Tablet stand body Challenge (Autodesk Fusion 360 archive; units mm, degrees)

design "mmTablet stand body Challenge" references "haas minimill"
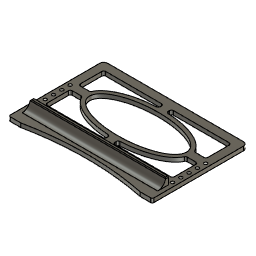
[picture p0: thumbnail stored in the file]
sketch "Sketch1" plane through (0, 0, 0) normal (0, 0, 1) x axis (1, 0, 0)
  line L1 (225.425, 0) -> (0, 0)
  line L2 (225.425, 149.225) -> (225.425, 0)
  line L3 (0, 149.225) -> (225.425, 149.225)
  line L4 (0, 0) -> (0, 149.225)
  point P1 (0, 0)
  point P2 (0, 0)
  point P3 (225.425, 0)
  point P5 (0, 149.225)
  horizontal L1
  vertical L2
  horizontal L3
  vertical L4
  coincident P1 P2
  dimension "d1" distance P2 P3 = 225.425
  dimension "d2" distance P2 P5 = 149.225
extrude "Extrude1" new body sketch "Sketch1" along normal blind 6.35
sketch "Sketch2" plane through (225.425, 0, 0) normal (1, 0, 0) x axis (0, 1, 0)
  line L1 (149.225, 0) -> (0, 0)
  line L2 (149.225, 6.35) -> (149.225, 0)
  line L3 (0, 6.35) -> (149.225, 6.35)
  line L4 (0, 0) -> (0, 6.35)
  line L5 (15.875, 6.35) -> (0, 6.35)
  line L6 (28.575, 6.35) -> (15.875, 6.35)
  line L7 (28.575, 17.907) -> (28.575, 6.35)
  line L8 (31.75, 17.907) -> (28.575, 17.907)
  line L9 (31.75, 6.35) -> (31.75, 17.907)
  line L10 (28.575, 6.35) -> (31.75, 6.35)
  line L11 (27.305, 6.35) -> (28.575, 6.35)
  line L12 (27.305, 16.637) -> (27.305, 6.35)
  line L13 (27.305, 16.637) -> (28.575, 17.907)
  line L14 (34.0111, 17.907) -> (28.575, 17.907)
  point P5 (0, 6.35)
  point P6 (0, 6.35)
  point P11 (31.75, 6.35)
  point P7 (15.875, 6.35)
  point P8 (28.575, 6.35)
  point P9 (28.575, 17.907)
  point P10 (31.75, 17.907)
  point P12 (27.305, 6.35)
  coincident P5 P6
  perpendicular L4 L5
  parallel L3 L6
  perpendicular L6 L7
  perpendicular L7 L8
  coincident L3 P11
  perpendicular L3 L9
  perpendicular L7 L11
  perpendicular L6 L12
  horizontal L14
  dimension "d5" distance P6 P7 = 15.875
  dimension "d6" distance P7 P8 = 12.7
  dimension "d8" distance P8 P9 = 11.557
  dimension "d9" distance P9 P10 = 3.175
  dimension "d10" distance P8 P12 = 1.27
  dimension "d11" angle L13 L14 = 135
extrude "Extrude2" add sketch "Sketch2" profile of L3 L6 L7 L8 L9 L10 L11 L12 L13 against normal blind 225.425
fillet "Fillet1" radius 12.7
sketch "Sketch3" plane through (0, 0, 6.35) normal (0, 0, 1) x axis (-1, 0, 0)
  line L1 (0, -14.8363) -> (-225.425, -14.8363)
  line L2 (0, 0) -> (0, -14.8363)
  line L3 (-225.425, 0) -> (0, 0)
  line L4 (-225.425, -14.8363) -> (-225.425, 0)
  line L5 (-19.05, 0) -> (0, 0)
  line L6 (-206.375, 0) -> (-225.425, 0)
  line L7 (-206.375, 0) -> (-19.05, 0)
  arc A1 centre (-112.7125, 457.2) radius 466.6953 clockwise from (-19.05, 0) to (-206.375, 0)
  point P4 (0, 0)
  point P6 (0, 0)
  point P5 (-225.425, 0)
  point P8 (-225.425, 0)
  point P7 (-19.05, 0)
  point P9 (-206.375, 0)
  point P10 (-112.7125, 457.2)
  coincident P4 P6
  perpendicular L2 L5
  coincident P5 P8
  perpendicular L4 L6
  dimension "d16" distance P6 P7 = 19.05
  dimension "d17" distance P8 P9 = 19.05
  dimension "d18" distance L3 P10 = 457.2
extrude "Extrude3" cut sketch "Sketch3" profile of L3 A1 L7 against normal blind 6.35
sketch "Sketch4" plane through (0, 0, 17.907) normal (0, 0, 1) x axis (-1, 0, 0)
  line L1 (-225.425, -31.75) -> (-225.425, -28.575)
  line L2 (0, -31.75) -> (-225.425, -31.75)
  line L3 (0, -28.575) -> (0, -31.75)
  line L4 (-225.425, -28.575) -> (0, -28.575)
  line L5 (-6.35, -31.75) -> (0, -31.75)
  line L6 (-6.35, -12.7) -> (-6.35, -31.75)
  line L7 (0, -12.7) -> (-6.35, -12.7)
  line L8 (0, -31.75) -> (0, -12.7)
  point P4 (0, -31.75)
  point P6 (0, -31.75)
  point P7 (-6.35, -31.75)
  point P9 (0, -12.7)
  horizontal L5
  vertical L6
  horizontal L7
  vertical L8
  coincident P4 P6
  dimension "d21" distance P6 P7 = 6.35
  dimension "d22" distance P6 P9 = 19.05
work_plane "WorkPlane1"
extrude "Extrude4" cut sketch "Sketch4" profile of L2 L3 L4 L5 L6 L7 L8 to an object
sketch "Sketch5" plane through (0, 0, 17.907) normal (0, 0, 1) x axis (-1, 0, 0)
  line L1 (-6.35, -28.575) -> (-6.35, -31.75)
  line L2 (-225.425, -28.575) -> (-6.35, -28.575)
  line L3 (-225.425, -31.75) -> (-225.425, -28.575)
  line L4 (-6.35, -31.75) -> (-225.425, -31.75)
  line L5 (-219.075, -31.75) -> (-225.425, -31.75)
  line L6 (-219.075, -12.7) -> (-219.075, -31.75)
  line L7 (-225.425, -12.7) -> (-219.075, -12.7)
  line L8 (-225.425, -31.75) -> (-225.425, -12.7)
  point P5 (-225.425, -31.75)
  point P6 (-225.425, -31.75)
  point P7 (-219.075, -31.75)
  point P9 (-225.425, -12.7)
  horizontal L5
  vertical L6
  horizontal L7
  vertical L8
  coincident P5 P6
  dimension "d25" distance P6 P7 = 6.35
  dimension "d26" distance P6 P9 = 19.05
extrude "Extrude5" cut sketch "Sketch5" profile of L2 L3 L4 L5 L6 L7 L8 to an object
chamfer "Chamfer1" distance 1.27
sketch "Sketch6" plane through (0, 0, 6.35) normal (0, 0, 1) x axis (-1, 0, 0)
  line L1 (-225.425, -149.225) -> (-225.425, 0)
  line L2 (0, -149.225) -> (-225.425, -149.225)
  line L3 (0, 0) -> (0, -149.225)
  line L4 (-19.05, 0) -> (0, 0)
  line L5 (-225.425, 0) -> (-206.375, 0)
  line L6 (-219.075, -14.8363) -> (-219.075, -31.75)
  line L7 (-6.35, -14.8363) -> (-219.075, -14.8363)
  line L8 (-6.35, -31.75) -> (-6.35, -14.8363)
  line L9 (-219.075, -31.75) -> (-6.35, -31.75)
  line L10 (-112.7125, -31.75) -> (-112.7125, -149.225)
  line L11 (-225.425, -90.4875) -> (-112.7125, -90.4875)
  curve K1 (-188.9125, -90.4875) -> (-36.5125, -90.4875)
  curve K2 (-112.7125, -122.2375) -> (-112.7125, -58.7375)
  arc A1 centre (-112.7125, 457.2) radius 466.6953 clockwise from (-19.05, 0) to (-206.375, 0)
  closed curve K3 centre (-112.7125, -90.4875)
  point P13 (-112.7125, -149.225)
  point P14 (-112.7125, -31.75)
  point P15 (-112.7125, -90.4875)
  point P18 (-36.5125, -90.4875)
  point P19 (-188.9125, -90.4875)
  point P20 (-112.7125, -58.7375)
  point P21 (-112.7125, -122.2375)
  point P17 (-112.7125, -90.4875)
  point P16 (-225.425, -90.4875)
  midpoint L2 P13
  midpoint L9 P14
  midpoint L10 P15
  perpendicular L10 L11
  coincident K3 P18
  coincident K3 P19
  coincident K3 P20
  coincident K3 P21
  coincident P15 P17
  perpendicular L10 K1
  coincident L1 P16
  dimension "d37" distance K3 = 152.4
  dimension "d38" = 31.75
extrude "Extrude6" cut sketch "Sketch6" profile of L10 L11 K3 no distance stored
sketch "Sketch7" plane through (0, 0, 6.35) normal (0, 0, 1) x axis (-1, 0, 0)
  line L1 (-212.725, -136.525) -> (-12.7, -136.525)
  line L2 (-212.725, -44.45) -> (-212.725, -136.525)
  line L3 (-12.7, -44.45) -> (-212.725, -44.45)
  line L4 (-12.7, -136.525) -> (-12.7, -44.45)
  line L5 (-225.425, -149.225) -> (-225.425, 0)
  line L6 (0, -149.225) -> (-225.425, -149.225)
  line L7 (0, 0) -> (0, -149.225)
  line L8 (-19.05, 0) -> (0, 0)
  line L9 (-225.425, 0) -> (-206.375, 0)
  line L10 (-219.075, -14.8363) -> (-219.075, -31.75)
  line L11 (-6.35, -14.8363) -> (-219.075, -14.8363)
  line L12 (-6.35, -31.75) -> (-6.35, -14.8363)
  line L13 (-219.075, -31.75) -> (-6.35, -31.75)
  line L14 (-106.3625, -90.4875) -> (-112.7125, -90.4875)
  line L15 (-112.7125, -44.45) -> (-112.7125, -90.4875)
  line L16 (-112.7125, -136.525) -> (-112.7125, -90.4875)
  line L17 (-106.3625, -84.1375) -> (-106.3625, -90.4875)
  line L18 (-106.3625, -44.45) -> (-106.3625, -52.5004)
  line L19 (-119.0625, -84.1375) -> (-119.0625, -90.4875)
  line L20 (-119.0625, -44.45) -> (-119.0625, -52.5004)
  line L21 (-106.3625, -122.1271) -> (-106.3625, -90.4875)
  line L22 (-106.3625, -136.525) -> (-106.3625, -128.4746)
  line L23 (-119.0625, -122.1271) -> (-119.0625, -90.4875)
  line L24 (-119.0625, -136.525) -> (-119.0625, -128.4746)
  line L25 (-119.0625, -84.1375) -> (-112.7125, -84.1375)
  line L26 (-212.725, -84.1375) -> (-194.1079, -84.1375)
  line L27 (-119.0625, -96.8375) -> (-112.7125, -96.8375)
  line L28 (-212.725, -96.8375) -> (-194.1079, -96.8375)
  line L29 (-119.0625, -90.4875) -> (-112.7125, -90.4875)
  line L30 (-195.2625, -90.4875) -> (-188.9125, -90.4875)
  line L31 (-38.0521, -84.1375) -> (-112.7125, -84.1375)
  line L32 (-12.7, -84.1375) -> (-31.3171, -84.1375)
  line L33 (-38.0521, -96.8375) -> (-112.7125, -96.8375)
  line L34 (-12.7, -96.8375) -> (-31.3171, -96.8375)
  closed curve K1 centre (-112.7125, -90.4875)
  arc A1 centre (-112.7125, 457.2) radius 466.6953 clockwise from (-19.05, 0) to (-206.375, 0)
  closed curve K2 centre (-112.7125, -90.4875)
  closed curve K3 centre (-112.7125, -90.4875)
  point P6 (-112.7125, -90.4875)
  point P20 (-112.7125, -90.4875)
  point P18 (-112.7125, -90.4875)
  point P21 (-112.7125, -90.4875)
  point P22 (-112.7125, -44.45)
  point P23 (-112.7125, -90.4875)
  point P24 (-112.7125, -136.525)
  point P39 (-106.3625, -84.1375)
  point P41 (-119.0625, -52.5004)
  point P42 (-106.3625, -52.5004)
  point P43 (-106.3625, -122.1271)
  point P44 (-106.3625, -128.4746)
  point P45 (-119.0625, -122.1271)
  point P46 (-119.0625, -128.4746)
  point P47 (-119.0625, -96.8375)
  point P48 (-194.1079, -96.8375)
  point P49 (-194.1079, -84.1375)
  point P50 (-188.9125, -90.4875)
  point P51 (-195.2625, -90.4875)
  point P52 (-38.0521, -84.1375)
  point P53 (-31.3171, -84.1375)
  point P54 (-38.0521, -96.8375)
  point P55 (-31.3171, -96.8375)
  horizontal L1
  vertical L2
  horizontal L3
  vertical L4
  coincident P6 P20
  perpendicular L2 L29
  coincident P18 P21
  midpoint L3 P22
  perpendicular L3 L15
  coincident P18 P23
  midpoint L1 P24
  coincident P39 L31
  collinear L17 L18
  collinear L19 L20
  coincident K3 P41
  coincident K3 P42
  coincident K1 P43
  coincident K3 P44
  collinear L21 L22
  coincident K1 P45
  coincident K3 P46
  collinear L23 L24
  collinear L25 L26
  coincident L23 P47
  collinear L27 L28
  coincident K3 P48
  coincident K3 P49
  coincident K1 P50
  collinear L29 L30
  coincident K3 P51
  coincident K1 P52
  coincident K3 P53
  collinear L31 L32
  coincident K1 P54
  coincident K3 P55
  collinear L33 L34
  dimension "d65" distance L1 L6 = 12.7
  dimension "d66" distance L2 L5 = 12.7 (= "d65")
  dimension "d67" distance L3 L13 = 12.7
  dimension "d68" = 38.1
extrude "Extrude7" cut sketch "Sketch7" profile of L1 L2 L3 L4 K3 L24 L22 L26 L32 L28 L34 L18 L20 no distance stored
fillet "Fillet2" radius 3
fillet "Fillet3" radius 3
hole "Hole1" HoleDepth 35.56 HoleDiameter 5.035 TipAngle 118 RefDim1 6.35 RefDim2 38.1
rectangular_pattern "R-Pattern1" uSpaceDistance -52.07 vSpaceDistance 212.725
fillet "Fillet4" radius 6
fillet "Fillet5" radius 2.5
fillet "Fillet6" radius 2.5
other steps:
thread "Thread1"

design "haas minimill"
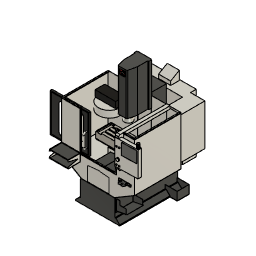
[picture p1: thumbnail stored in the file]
